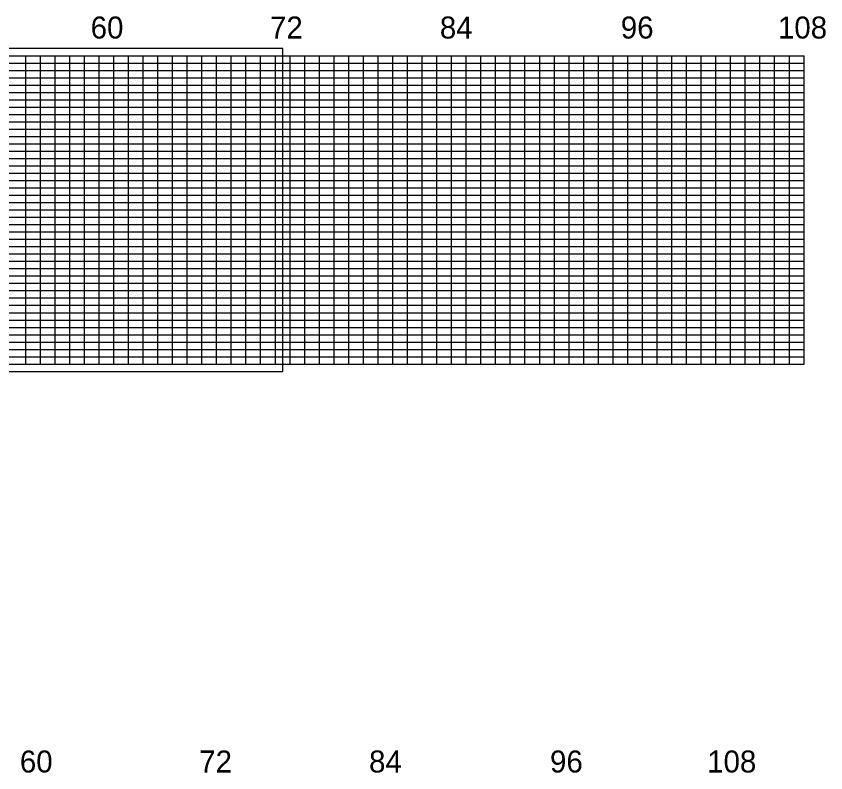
# Model space of a CAD drawing. Extents: x 1914168 to 1925341, y 720939 to 777401.
# Drawn here: x 1917112 to 1919868, y 767072 to 769649 of the extents above; entities that cross this region are included whole.
import ezdxf

# ---------------------------------------------------------------- set-up
doc = ezdxf.new("R2010")
doc.units = 0
doc.layers.add('RD_PD_WallFill', color=7, linetype='Continuous')
doc.layers.add('RD_SHT_IplotShp', color=7, linetype='Continuous')

msp = doc.modelspace()

# ---------------------------------------------------------------- linework, layer by layer
at = {"layer": 'RD_PD_WallFill'}
for p, q in [((1914444.2, 769514.1), (1919794.2, 769514.2)), ((1917144.2, 768464.2), (1917144.2, 769514.2)), ((1917194.2, 768464.2), (1917194.2, 769514.2)), ((1917244.2, 768464.2), (1917244.2, 769514.2)), ((1917294.2, 768464.2), (1917294.2, 769514.2)), ((1917344.2, 768464.2), (1917344.2, 769514.2)), ((1917394.2, 768464.2), (1917394.2, 769514.2)), ((1917444.2, 768464.2), (1917444.2, 769514.2)), ((1917494.2, 768464.2), (1917494.2, 769514.2)), ((1917544.2, 768464.1), (1917544.2, 769514.2)), ((1917594.2, 768464.2), (1917594.2, 769514.2)), ((1917644.2, 768464.2), (1917644.2, 769514.2)), ((1917694.2, 768464.2), (1917694.2, 769514.2)), ((1917744.2, 768464.2), (1917744.2, 769514.2)), ((1917794.2, 768464.2), (1917794.2, 769514.2)), ((1917844.2, 768464.1), (1917844.2, 769514.2)), ((1917894.2, 768464.1), (1917894.2, 769514.2)), ((1917944.2, 768464.2), (1917944.2, 769514.2)), ((1917994.2, 768464.2), (1917994.2, 769514.2)), ((1918044.2, 768464.2), (1918044.2, 769514.2)), ((1918094.2, 768464.2), (1918094.2, 769514.2)), ((1918144.2, 768464.2), (1918144.2, 769514.2)), ((1918194.2, 768464.2), (1918194.2, 769514.2)), ((1918244.2, 768464.2), (1918244.2, 769514.2)), ((1918294.2, 768464.2), (1918294.2, 769514.2)), ((1918344.2, 768464.2), (1918344.2, 769514.2)), ((1918394.2, 768464.2), (1918394.2, 769514.2)), ((1918444.2, 768464.2), (1918444.2, 769514.2)), ((1918494.2, 768464.2), (1918494.2, 769514.2)), ((1918544.2, 768464.2), (1918544.2, 769514.2)), ((1918594.2, 768464.2), (1918594.2, 769514.2)), ((1918644.2, 768464.2), (1918644.2, 769514.2)), ((1918694.2, 768464.2), (1918694.2, 769514.2)), ((1918744.2, 768464.2), (1918744.2, 769514.2)), ((1918794.2, 768464.2), (1918794.2, 769514.2)), ((1918844.2, 768464.2), (1918844.2, 769514.2)), ((1918894.2, 768464.2), (1918894.2, 769514.2)), ((1918944.2, 768464.2), (1918944.2, 769514.2)), ((1918994.2, 768464.2), (1918994.2, 769514.2)), ((1919044.2, 768464.2), (1919044.2, 769514.2)), ((1919094.2, 768464.2), (1919094.2, 769514.2)), ((1919144.2, 768464.2), (1919144.2, 769514.2)), ((1919194.2, 768464.2), (1919194.2, 769514.2)), ((1919244.2, 768464.2), (1919244.2, 769514.2)), ((1919294.2, 768464.2), (1919294.2, 769514.2)), ((1919344.2, 768464.2), (1919344.2, 769514.2)), ((1919394.2, 768464.2), (1919394.2, 769514.2)), ((1919444.2, 768464.2), (1919444.2, 769514.2)), ((1919494.2, 768464.2), (1919494.2, 769514.2)), ((1919544.2, 768464.2), (1919544.2, 769514.2)), ((1919594.2, 768464.2), (1919594.2, 769514.2)), ((1919644.2, 768464.2), (1919644.2, 769514.2)), ((1919694.2, 768464.2), (1919694.2, 769514.2)), ((1919744.2, 768464.2), (1919744.2, 769514.2)), ((1919794.2, 768464.2), (1919794.2, 769514.2)), ((1914894.2, 769489.1), (1919794.2, 769489.1)), ((1914894.2, 769464.1), (1919794.2, 769464.1)), ((1914894.2, 769439.1), (1919794.2, 769439.1)), ((1914894.2, 769414.2), (1919794.2, 769414.1)), ((1914894.2, 769389.1), (1919794.2, 769389.2)), ((1914444.2, 769364.1), (1919794.2, 769364.1)), ((1914444.2, 769339.1), (1919794.2, 769339.1)), ((1914444.2, 769314.1), (1919794.2, 769314.2)), ((1914444.2, 769289.2), (1919794.2, 769289.1)), ((1914444.2, 769264.2), (1919794.2, 769264.2)), ((1914444.2, 769239.1), (1919794.2, 769239.1)), ((1914444.2, 769214.1), (1919794.2, 769214.1)), ((1914444.2, 769189.2), (1919794.2, 769189.1)), ((1914444.2, 769164.1), (1919794.2, 769164.1)), ((1914444.2, 769139.2), (1919794.2, 769139.1)), ((1914444.2, 769114.1), (1919794.2, 769114.1)), ((1914444.2, 769089.1), (1919794.2, 769089.2)), ((1914444.2, 769064.1), (1919794.2, 769064.1)), ((1914444.2, 769039.1), (1919794.2, 769039.2)), ((1914444.2, 769014.1), (1919794.2, 769014.1)), ((1914444.2, 768989.1), (1919794.2, 768989.1)), ((1914444.2, 768964.2), (1919794.2, 768964.1)), ((1914444.2, 768939.1), (1919794.2, 768939.1)), ((1914444.2, 768914.1), (1919794.2, 768914.1)), ((1914444.2, 768889.1), (1919794.2, 768889.1)), ((1914444.2, 768864.1), (1919794.2, 768864.2)), ((1914444.2, 768839.1), (1919794.2, 768839.1)), ((1914444.2, 768814.1), (1919794.2, 768814.1)), ((1914444.2, 768789.1), (1919794.2, 768789.1)), ((1914444.2, 768764.1), (1919794.2, 768764.1)), ((1914444.2, 768739.1), (1919794.2, 768739.1)), ((1914444.2, 768714.1), (1919794.2, 768714.1)), ((1914444.2, 768689.1), (1919794.2, 768689.1)), ((1914444.2, 768664.1), (1919794.2, 768664.1)), ((1914444.2, 768639.1), (1919794.2, 768639.1)), ((1914444.2, 768614.1), (1919794.2, 768614.1)), ((1914444.2, 768589.1), (1919794.2, 768589.1)), ((1914444.2, 768564.1), (1919794.2, 768564.1)), ((1914444.2, 768539.1), (1919794.2, 768539.1)), ((1914444.2, 768514.1), (1919794.2, 768514.1)), ((1914494.2, 768489.1), (1919794.2, 768489.1)), ((1914444.2, 768464.1), (1919794.2, 768464.1))]:
    msp.add_line(p, q, dxfattribs=at)
at = {"layer": 'RD_SHT_IplotShp'}
msp.add_lwpolyline([(1914419.2, 768439.1), (1918019.2, 768439.1), (1918019.2, 769539.1), (1914419.2, 769539.1)], close=True, dxfattribs=at)

# ---------------------------------------------------------------- texts
at = {"layer": 'RD_PD_WallFill'}
for s, p in [('60', (1917365.4, 769572.8)), ('72', (1917976, 769572.8)), ('84', (1918554.3, 769572.8)), ('96', (1919170.4, 769572.8)), ('108', (1919705.4, 769572.8)), ('60', (1917124.4, 767072.8)), ('72', (1917735.1, 767072.8)), ('84', (1918313.3, 767072.8)), ('96', (1918929.4, 767072.8)), ('108', (1919464.4, 767072.8))]:
    msp.add_text(s, height=75, dxfattribs=at).set_placement(p)

doc.saveas('drawing.dxf')
